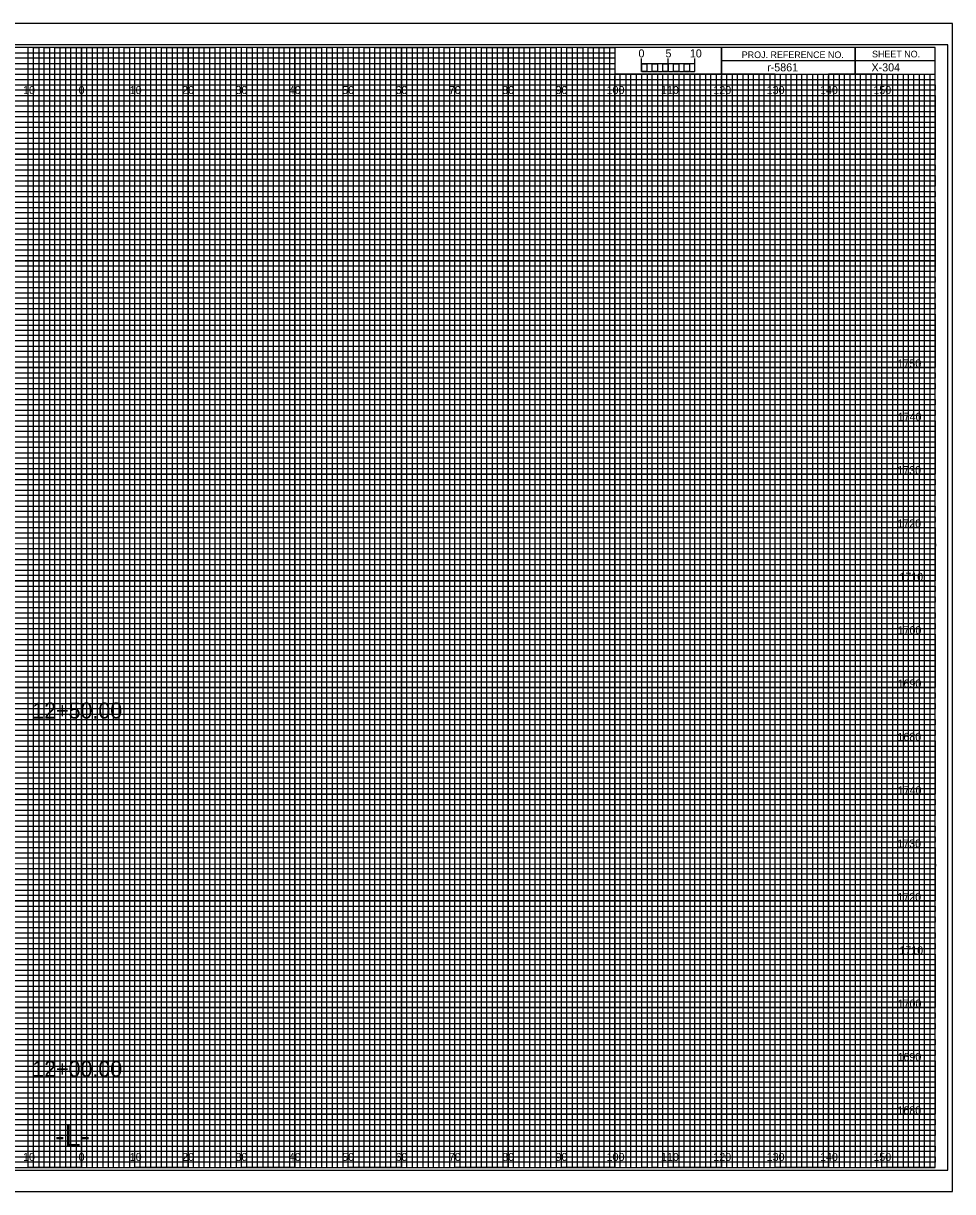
# Model space of a CAD drawing. Extents: x -15 to 323, y -5 to 6170.
# Drawn here: x 149.1 to 323.3, y -4.5 to 214.5 of the extents above; entities that cross this region are included whole.
import ezdxf

# ---------------------------------------------------------------- set-up
doc = ezdxf.new("R2010")
doc.units = 0
for name, color, linetype in [('Prop XS Alignment Label', 7, 'Continuous'), ('Prop XS Bar Scale Labels', 7, 'Continuous'), ('Prop XS DDE', 7, 'Continuous'), ('Prop XS DDE Earthwork Shape', 7, 'Continuous'), ('Prop XS DDE Slope Text', 7, 'Continuous'), ('Prop XS DDE Text', 7, 'Continuous'), ('Prop XS Earthwork Shape', 7, 'Continuous'), ('Prop XS Noise Wall', 7, 'Continuous'), ('Prop XS Project Number', 7, 'Continuous'), ('Prop XS Retaining Wall', 7, 'Continuous'), ('Prop XS Station Labels', 7, 'Continuous'), ('Prop XS Temporary Shoring', 7, 'Continuous'), ('Scratch_Level_3', 7, 'Continuous'), ('Scratch_Level_7', 7, 'Continuous'), ('Scratch_Level_8', 7, 'Continuous'), ('Sheet Cross Section Grid Minor 1 CELL', 7, 'Continuous')]:
    doc.layers.add(name, color=color, linetype=linetype)

msp = doc.modelspace()

# ---------------------------------------------------------------- linework, layer by layer
at = {"layer": 'Prop XS Alignment Label'}
for p, q in [((265, 205.49), (265, 207.9)), ((265, 206.9), (265, 207.9)), ((270, 205.49), (270, 207.9)), ((275, 205.49), (275, 207.9)), ((275, 206.9), (275, 207.9))]:
    msp.add_line(p, q, dxfattribs=at)
for points in [[(275, 206.9), (265, 206.9), (265, 205.49), (275, 205.49)], [(265, 206.9), (266, 206.9), (266, 205.49), (265, 205.49)], [(267, 206.9), (268, 206.9), (268, 205.49), (267, 205.49)], [(269, 206.9), (270, 206.9), (270, 205.49), (269, 205.49)], [(271, 206.9), (272, 206.9), (272, 205.49), (271, 205.49)], [(273, 206.9), (274, 206.9), (274, 205.49), (273, 205.49)]]:
    msp.add_lwpolyline(points, close=True, dxfattribs=at)
at = {"layer": 'Prop XS DDE'}
msp.add_lwpolyline([(-13.4, -4.5), (323.3, -4.5), (323.3, 214.5), (-13.4, 214.5)], close=True, dxfattribs=at)
at = {"layer": 'Prop XS DDE Slope Text'}
msp.add_lwpolyline([(-10.8, -0.5), (322.4, -0.5), (322.4, 210.5), (-10.8, 210.5)], close=True, dxfattribs=at)
at = {"layer": 'Prop XS DDE Text'}
for p, q in [((150, 0), (150, 210)), ((160, 0), (160, 210)), ((170, 0), (170, 210)), ((180, 0), (180, 210)), ((190, 0), (190, 210)), ((200, 0), (200, 210)), ((210, 0), (210, 210)), ((220, 0), (220, 210)), ((230, 0), (230, 210)), ((240, 0), (240, 210)), ((250, 0), (250, 210)), ((260, 0), (260, 204.69)), ((270, 0), (270, 204.69)), ((280, 0), (280, 204.69)), ((290, 0), (290, 204.69)), ((300, 0), (300, 204.69)), ((310, 0), (310, 204.69)), ((0, 200), (320, 200)), ((0, 190), (320, 190)), ((0, 180), (320, 180)), ((0, 170), (320, 170)), ((0, 160), (320, 160)), ((0, 150), (320, 150)), ((0, 140), (320, 140)), ((0, 130), (320, 130)), ((0, 120), (320, 120)), ((0, 110), (320, 110)), ((0, 100), (320, 100)), ((0, 90), (320, 90)), ((0, 80), (320, 80)), ((0, 70), (320, 70)), ((0, 60), (320, 60)), ((0, 50), (320, 50)), ((0, 40), (320, 40)), ((0, 30), (320, 30)), ((0, 20), (320, 20)), ((0, 10), (320, 10))]:
    msp.add_line(p, q, dxfattribs=at)
at = {"layer": 'Prop XS Earthwork Shape'}
for p, q in [((150, 210), (140, 210)), ((150, 0), (150, 210)), ((170, 210), (160, 210)), ((160, 210), (160, 0)), ((170, 0), (170, 210)), ((190, 210), (180, 210)), ((180, 210), (180, 0)), ((190, 0), (190, 210)), ((210, 210), (200, 210)), ((200, 210), (200, 0)), ((210, 0), (210, 210)), ((230, 210), (220, 210)), ((220, 210), (220, 0)), ((230, 0), (230, 210)), ((250, 210), (240, 210)), ((240, 210), (240, 0)), ((250, 0), (250, 210)), ((260, 210), (260, 0)), ((270, 0), (270, 205)), ((290, 205), (280, 205)), ((280, 205), (280, 0)), ((290, 0), (290, 205)), ((310, 205), (300, 205)), ((300, 205), (300, 0)), ((310, 0), (310, 205)), ((160, 0), (150, 0)), ((180, 0), (170, 0)), ((200, 0), (190, 0)), ((220, 0), (210, 0)), ((240, 0), (230, 0)), ((260, 0), (250, 0)), ((280, 0), (270, 0)), ((300, 0), (290, 0)), ((320, 0), (310, 0)), ((320, 0), (320, 0))]:
    msp.add_line(p, q, dxfattribs=at)
for points in [[(0, 200), (320, 200), (320, 190), (0, 190)], [(0, 180), (320, 180), (320, 170), (0, 170)], [(0, 160), (320, 160), (320, 150), (0, 150)], [(0, 140), (320, 140), (320, 130), (0, 130)], [(0, 120), (320, 120), (320, 110), (0, 110)], [(0, 100), (320, 100), (320, 90), (0, 90)], [(0, 80), (320, 80), (320, 70), (0, 70)], [(0, 60), (320, 60), (320, 50), (0, 50)], [(0, 40), (320, 40), (320, 30), (0, 30)], [(0, 20), (320, 20), (320, 10), (0, 10)]]:
    msp.add_lwpolyline(points, dxfattribs=at)
at = {"layer": 'Prop XS Noise Wall'}
for p, q in [((305, 210), (305, 205)), ((305, 205), (305, 210)), ((280, 207.5), (280, 205)), ((320, 207.49), (280, 207.49)), ((280, 205), (320, 205))]:
    msp.add_line(p, q, dxfattribs=at)
for points in [[(320, 210), (0, 210), (0, 0), (320, 0)], [(280, 210), (260, 210), (260, 205.03), (280, 205.03)], [(320, 210), (280, 210), (280, 205), (320, 205)]]:
    msp.add_lwpolyline(points, close=True, dxfattribs=at)
at = {"layer": 'Prop XS Retaining Wall'}
for p, q in [((267, 205), (266.01, 205)), ((266.01, 205), (266.01, 0)), ((267, 0), (267, 205)), ((269, 205), (268, 205)), ((268, 205), (268, 0)), ((269, 0), (269, 205)), ((266.01, 0), (265, 0)), ((268, 0), (267, 0))]:
    msp.add_line(p, q, dxfattribs=at)
for points in [[(150, 0), (151, 0), (151, 210), (152, 210), (152, 0)], [(152, 0), (153, 0), (153, 210), (154, 210), (154, 0)], [(155, 0), (156, 0), (156, 210), (157, 210), (157, 0)], [(157, 0), (158, 0), (158, 210), (159, 210), (159, 0)], [(160, 0), (161, 0), (161, 210), (162, 210), (162, 0)], [(162, 0), (163, 0), (163, 210), (164, 210), (164, 0)], [(165, 0), (166, 0), (166, 210), (167, 210), (167, 0)], [(167, 0), (168, 0), (168, 210), (169, 210), (169, 0)], [(170, 0), (171, 0), (171, 210), (172, 210), (172, 0)], [(172, 0), (173, 0), (173, 210), (174, 210), (174, 0)], [(175, 0), (176, 0), (176, 210), (177, 210), (177, 0)], [(177, 0), (178, 0), (178, 210), (179, 210), (179, 0)], [(180, 0), (181, 0), (181, 210), (182, 210), (182, 0)], [(182, 0), (183, 0), (183, 210), (184, 210), (184, 0)], [(185, 0), (186, 0), (186, 210), (187, 210), (187, 0)], [(187, 0), (188, 0), (188, 210), (189, 210), (189, 0)], [(190, 0), (191, 0), (191, 210), (192, 210), (192, 0)], [(192, 0), (193, 0), (193, 210), (194, 210), (194, 0)], [(195, 0), (196, 0), (196, 210), (197, 210), (197, 0)], [(197, 0), (198, 0), (198, 210), (199, 210), (199, 0)], [(200, 0), (201, 0), (201, 210), (202, 210), (202, 0)], [(202, 0), (203, 0), (203, 210), (204, 210), (204, 0)], [(205, 0), (206, 0), (206, 210), (207, 210), (207, 0)], [(207, 0), (208, 0), (208, 210), (209, 210), (209, 0)], [(210, 0), (211, 0), (211, 210), (212, 210), (212, 0)], [(212, 0), (213, 0), (213, 210), (214, 210), (214, 0)], [(215, 0), (216, 0), (216, 210), (217, 210), (217, 0)], [(217, 0), (218, 0), (218, 210), (219, 210), (219, 0)], [(220, 0), (221, 0), (221, 210), (222, 210), (222, 0)], [(222, 0), (223, 0), (223, 210), (224, 210), (224, 0)], [(225, 0), (226, 0), (226, 210), (227, 210), (227, 0)], [(227, 0), (228, 0), (228, 210), (229, 210), (229, 0)], [(230, 0), (231, 0), (231, 210), (232, 210), (232, 0)], [(232, 0), (233, 0), (233, 210), (234, 210), (234, 0)], [(235, 0), (236, 0), (236, 210), (237, 210), (237, 0)], [(237, 0), (238, 0), (238, 210), (239, 210), (239, 0)], [(240, 0), (241, 0), (241, 210), (242, 210), (242, 0)], [(242, 0), (243, 0), (243, 210), (244, 210), (244, 0)], [(245, 0), (246, 0), (246, 210), (247, 210), (247, 0)], [(247, 0), (248, 0), (248, 210), (249, 210), (249, 0)], [(250, 0), (251, 0), (251, 210), (252, 210), (252, 0)], [(252, 0), (253, 0), (253, 210), (254, 210), (254, 0)], [(255, 0), (256, 0), (256, 210), (257, 210), (257, 0)], [(257, 0), (258, 0), (258, 210), (259, 210), (259, 0)], [(260, 0), (261, 0), (261, 205), (262.02, 205), (262.02, 0)], [(262, 0), (263, 0), (263, 205), (263.99, 205), (263.99, 0)], [(270, 0), (270.98, 0), (270.98, 205), (272, 205), (272, 0)], [(272, 0), (273, 0), (273, 205), (274.05, 205), (274.05, 0)], [(275, 0), (276, 0), (276, 205), (277, 205), (277, 0)], [(277, 0), (278, 0), (278, 205), (279, 205), (279, 0)], [(280, 0), (281, 0), (281, 205), (282, 205), (282, 0)], [(282, 0), (283, 0), (283, 205), (284, 205), (284, 0)], [(285, 0), (286, 0), (286, 205), (287, 205), (287, 0)], [(287, 0), (288, 0), (288, 205), (289, 205), (289, 0)], [(290, 0), (291, 0), (291, 205), (292, 205), (292, 0)], [(292, 0), (293, 0), (293, 205), (294, 205), (294, 0)], [(295, 0), (296, 0), (296, 205), (297, 205), (297, 0)], [(297, 0), (298, 0), (298, 205), (299, 205), (299, 0)], [(300, 0), (301, 0), (301, 205), (302, 205), (302, 0)], [(302, 0), (303, 0), (303, 205), (304, 205), (304, 0)], [(305, 0), (306, 0), (306, 205), (307, 205), (307, 0)], [(307, 0), (308, 0), (308, 205), (309, 205), (309, 0)], [(310, 0), (311, 0), (311, 205), (312, 205), (312, 0)], [(312, 0), (313, 0), (313, 205), (314, 205), (314, 0)], [(315, 0), (316, 0), (316, 205), (317, 205), (317, 0)], [(317, 0), (318, 0), (318, 205), (319, 205), (319, 0)]]:
    msp.add_lwpolyline(points, dxfattribs=at)
at = {"layer": 'Prop XS Station Labels'}
for points in [[(145, 0), (155, 0), (155, 210), (165, 210), (165, 0), (175, 0), (175, 210), (185, 210), (185, 0), (195, 0), (195, 210), (205, 210), (205, 0), (215, 0), (215, 210), (225, 210), (225, 0), (235, 0), (235, 210), (245, 210), (245, 0), (255, 0), (255, 210), (259.93, 210), (260, 210), (260, 205), (264.99, 205), (264.99, 0), (275, 0), (275, 205), (285, 205), (285, 0), (295, 0), (295, 205), (305, 205), (305, 0), (315, 0), (315, 205)], [(0, 205), (275, 205)], [(0, 185), (320, 185), (320, 195), (0, 195)], [(0, 165), (320, 165), (320, 175), (0, 175)], [(0, 145), (320, 145), (320, 155), (0, 155)], [(0, 125), (320, 125), (320, 135), (0, 135)], [(0, 105), (320, 105), (320, 115), (0, 115)], [(0, 85), (320, 85), (320, 95), (0, 95)], [(0, 65), (320, 65), (320, 75), (0, 75)], [(0, 45), (320, 45), (320, 55), (0, 55)], [(0, 25), (320, 25), (320, 35), (0, 35)], [(0, 5), (320, 5), (320, 15), (0, 15)]]:
    msp.add_lwpolyline(points, dxfattribs=at)
at = {"layer": 'Scratch_Level_7'}
for p, q in [((323.3, 214.5), (-13.4, 214.5)), ((-13.4, -4.5), (323.3, -4.5))]:
    msp.add_line(p, q, dxfattribs=at)
at = {"layer": 'Sheet Cross Section Grid Minor 1 CELL'}
for p, q in [((0, 209), (260, 209)), ((260, 209), (260, 207.98)), ((260, 207.98), (0, 207.98)), ((0, 207), (260, 207)), ((260, 205.89), (0, 205.89)), ((260, 207), (260, 205.89)), ((0, 204), (320, 204))]:
    msp.add_line(p, q, dxfattribs=at)
for points in [[(0, 203), (270, 203), (320, 203), (320, 202), (0, 202)], [(0, 201), (320, 201), (320, 199), (0, 199)], [(0, 198), (320, 198), (320, 197), (0, 196.98)], [(0, 196), (320, 196), (320, 194), (0, 194)], [(0, 193), (320, 193), (320, 192), (0, 192)], [(0, 191), (320, 191), (320, 189), (0, 189)], [(0, 188), (320, 188), (320, 187), (0, 187)], [(0, 186), (320, 186), (320, 184), (0, 184)], [(0, 183), (320, 183), (320, 182), (0, 182)], [(0, 181), (320, 181), (320, 179), (0, 179)], [(0, 178), (320, 178), (320, 177), (0, 177)], [(0, 176), (320, 176), (320, 173.95), (320, 173), (320, 172), (0, 172)], [(0, 174), (320, 174), (320, 173), (0, 173)], [(0, 171), (320, 171), (320, 169), (0, 169.03)], [(0, 169.03), (320, 169), (320, 168), (0, 168)], [(0, 167), (320, 167), (320, 166), (0, 166)], [(0, 164), (320, 164), (320, 163), (0, 163)], [(0, 162), (320, 162), (320, 161), (0, 161)], [(-0.07, 158.89), (320, 158.89), (320, 157.88), (-0.07, 157.88)], [(0, 157), (320, 157), (320, 156), (0, 156)], [(0, 154), (320, 154), (320, 153), (0, 153)], [(0, 152), (320, 152), (320, 151), (0, 151)], [(0, 149), (320, 149), (320, 148), (0, 148)], [(0, 147), (320, 147), (320, 146), (0, 146)], [(0, 144), (320, 144), (320, 143), (0, 143)], [(0, 142), (320, 142), (320, 141), (0, 141)], [(0, 139), (320, 139), (319.99, 137.98), (0, 138)], [(0, 137), (320, 137), (320, 136), (0, 136)], [(0, 134), (320, 134), (320, 133), (0, 133)], [(0, 132), (320, 132), (320, 131), (0, 131)], [(0, 129), (320, 129), (320, 128), (0, 128)], [(0, 127), (320, 127), (320, 126), (0, 126)], [(0, 124), (320, 124), (320, 123), (0, 123)], [(0, 122), (320, 122), (320, 121), (0, 121)], [(0, 119), (320, 119), (320, 118), (0, 118)], [(0, 116.99), (320.07, 116.91), (320, 116), (0, 116)], [(0, 114), (320, 114), (320, 113), (0, 113)], [(0, 112), (320, 112), (320, 111), (0, 111)], [(0, 109), (320, 109), (320, 108), (0, 108)], [(0, 107), (320, 107), (320, 106), (0, 106)], [(0, 104), (320, 104), (320, 103), (0, 103)], [(0, 102), (320, 102), (320, 101), (0, 101)], [(0, 99), (320, 99), (320, 98), (0, 98)], [(0, 97), (320, 97), (320, 96), (0, 96)], [(0, 94), (320, 94), (320, 93), (0, 93)], [(0, 92), (320, 92), (320, 91), (0, 91)], [(0, 89), (320, 89), (320, 88), (0, 88)], [(0, 87), (320, 87), (320, 86), (0, 86)], [(0, 84), (320, 84), (320, 83), (0, 83)], [(0, 82), (320, 82), (320, 81), (0, 81)], [(0, 79), (320, 79), (319.99, 77.98), (0, 78)], [(0, 77), (320, 77), (320, 76), (0, 76)], [(0, 74), (320, 74), (320, 73), (0, 73)], [(0, 72), (320, 72), (320, 71), (0, 71)], [(0, 69), (320, 69), (320, 68), (0, 68)], [(0, 67), (320, 67), (320, 66), (0, 66)], [(0, 64), (320, 64), (320, 63), (0, 63)], [(0, 62), (320, 62), (320, 61), (0, 61)], [(0, 59), (320, 59), (320, 58), (0, 58)], [(0, 56.99), (320.07, 56.91), (320, 56), (0, 56)], [(0, 54), (320, 54), (320, 53), (0, 53)], [(0, 52), (320, 52), (320, 51), (0, 51)], [(0, 49), (320, 49), (320, 48), (0, 48)], [(0, 47), (320, 47), (320, 46), (0, 46)], [(0, 44), (320, 44), (320, 43), (0, 43)], [(0, 42), (320, 42), (320, 41), (0, 41)], [(0, 39), (320, 39), (320, 38), (0, 38)], [(0, 37), (320, 37), (320, 36), (0, 36)], [(0, 34), (320, 34), (320, 33), (0, 33)], [(0, 32), (320, 32), (320, 31), (0, 31)], [(0, 29), (320, 29), (320, 28), (0, 28)], [(0, 27), (320, 27), (320, 26), (0, 26)], [(0, 24), (320, 24), (320, 23), (0, 23)], [(0, 22), (320, 22), (320, 21), (0, 21)], [(0, 19), (320, 19), (320, 18), (0, 18)], [(0, 17), (320, 17), (320, 16), (0, 16)], [(0, 14), (320, 14), (320, 13), (0, 13)], [(0, 12), (320, 12), (320, 11), (0, 11)], [(0, 9), (320, 9), (320, 8), (0, 8)], [(0, 7), (320, 7), (320, 6), (0, 6)], [(0, 4), (320, 4), (320, 3), (0, 3)], [(0, 2), (320, 2), (320, 1), (0, 1)]]:
    msp.add_lwpolyline(points, dxfattribs=at)

# ---------------------------------------------------------------- texts
at = {"layer": 'Prop XS Alignment Label'}
for s, height, p in [('0', 1.5, (264.41, 208.12)), ('-L-', 4, (155.06, 4))]:
    msp.add_text(s, height=height, dxfattribs=at).set_placement(p)
at = {"layer": 'Prop XS Bar Scale Labels'}
for s, p in [('5', (269.47, 208.12)), ('10', (274.04, 208.12))]:
    msp.add_text(s, height=1.5, dxfattribs=at).set_placement(p)
at = {"layer": 'Prop XS DDE Earthwork Shape'}
msp.add_text('X-304', height=1.5, dxfattribs=at).set_placement((308.09, 205.5))
at = {"layer": 'Prop XS Noise Wall'}
for s, p in [('PROJ. REFERENCE NO.', (283.77, 207.99)), ('SHEET NO.', (308.19, 208.12))]:
    msp.add_text(s, height=1.25, dxfattribs=at).set_placement(p)
at = {"layer": 'Prop XS Project Number'}
msp.add_text('r-5861', height=1.5, dxfattribs=at).set_placement((288.53, 205.5))
at = {"layer": 'Prop XS Temporary Shoring'}
for s, p in [('12+50.00', (150.77, 84.19)), ('12+00.00', (150.77, 17.02))]:
    msp.add_text(s, height=3, dxfattribs=at).set_placement(p)
at = {"layer": 'Scratch_Level_3'}
for s, p in [('1750', (312.96, 150)), ('1740', (313, 140)), ('1730', (312.92, 130)), ('1720', (312.93, 120)), ('1710', (313.31, 110)), ('1700', (312.98, 100)), ('1690', (312.97, 90)), ('1680', (312.95, 80)), ('1740', (313, 70)), ('1730', (312.92, 60)), ('1720', (312.93, 50)), ('1710', (313.31, 40)), ('1700', (312.98, 30)), ('1690', (312.97, 20)), ('1680', (312.95, 10))]:
    msp.add_text(s, height=1.5, dxfattribs=at).set_placement(p)
at = {"layer": 'Scratch_Level_8'}
for s, p in [('10', (149.04, 201.25)), ('0', (159.45, 201.25)), ('0', (159.45, 201.25)), ('10', (169.04, 201.25)), ('20', (178.86, 201.25)), ('30', (188.86, 201.25)), ('40', (198.86, 201.25)), ('50', (208.86, 201.25)), ('60', (218.86, 201.25)), ('70', (228.86, 201.25)), ('80', (238.86, 201.25)), ('90', (248.86, 201.25)), ('100', (258.44, 201.25)), ('110', (268.62, 201.25)), ('120', (278.44, 201.25)), ('130', (288.44, 201.25)), ('140', (298.44, 201.25)), ('150', (308.44, 201.25)), ('10', (149.04, 1.25)), ('0', (159.45, 1.25)), ('0', (159.45, 1.25)), ('10', (169.04, 1.25)), ('20', (178.86, 1.25)), ('30', (188.86, 1.25)), ('40', (198.86, 1.25)), ('50', (208.86, 1.25)), ('60', (218.86, 1.25)), ('70', (228.86, 1.25)), ('80', (238.86, 1.25)), ('90', (248.86, 1.25)), ('100', (258.44, 1.25)), ('110', (268.62, 1.25)), ('120', (278.44, 1.25)), ('130', (288.44, 1.25)), ('140', (298.44, 1.25)), ('150', (308.44, 1.25))]:
    msp.add_text(s, height=1.5, dxfattribs=at).set_placement(p)

doc.saveas('drawing.dxf')
